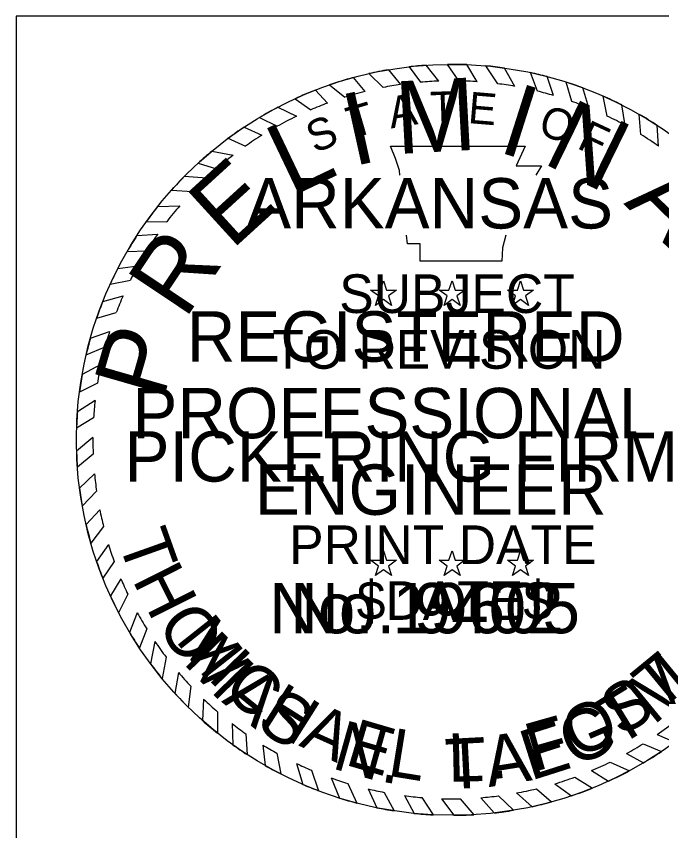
# Model space of a CAD drawing. Extents: x -0.3 to 2.65, y 0 to 1.9.
# Drawn here: x 1.2521 to 1.3416, y 0.0906 to 0.2035 of the extents above; entities that cross this region are included whole.
import ezdxf

# ---------------------------------------------------------------- set-up
doc = ezdxf.new("R2010")
doc.units = 0
for name, color, linetype in [('Level 50', 7, 'Continuous'), ('Level 51', 7, 'Continuous'), ('Level 53', 7, 'Continuous'), ('Level 55', 7, 'Continuous'), ('Level 56', 7, 'Continuous')]:
    doc.layers.add(name, color=color, linetype=linetype)

msp = doc.modelspace()

# ---------------------------------------------------------------- linework, layer by layer
at = {"layer": 'Level 50'}
msp.add_circle((1.3125000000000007, 0.14479166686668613), 0.05208333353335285, dxfattribs=at)
at = {"layer": 'Level 51'}
for p, q in [((1.3106664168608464, 0.194555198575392), (1.3089229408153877, 0.19675201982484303)), ((1.3134475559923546, 0.19457995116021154), (1.311890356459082, 0.1968714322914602)), ((1.3160059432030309, 0.19446539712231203), (1.314563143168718, 0.19683412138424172)), ((1.3188309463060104, 0.194184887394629), (1.3171991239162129, 0.19666258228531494)), ((1.3009818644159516, 0.19558542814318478), (1.302970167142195, 0.1936685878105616)), ((1.3036774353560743, 0.19612232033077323), (1.3053475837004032, 0.19407263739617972)), ((1.3065572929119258, 0.19653485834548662), (1.3081281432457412, 0.19439668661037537)), ((1.3212101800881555, 0.19382128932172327), (1.3197727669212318, 0.19636472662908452)), ((1.3243517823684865, 0.19315804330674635), (1.3233797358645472, 0.19572598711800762)), ((1.298814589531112, 0.19504485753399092), (1.3004232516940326, 0.19310236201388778)), ((1.3265952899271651, 0.1925524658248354), (1.3257055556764, 0.19517308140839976)), ((1.3291194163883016, 0.19173382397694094), (1.328330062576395, 0.19441104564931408)), ((1.2935701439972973, 0.19331314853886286), (1.2952165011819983, 0.19149339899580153)), ((1.2955130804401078, 0.19402700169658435), (1.297640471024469, 0.19232024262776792)), ((1.331456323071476, 0.19083978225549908), (1.3306495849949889, 0.19361037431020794)), ((1.2907339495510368, 0.19210881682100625), (1.2929100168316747, 0.1905737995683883)), ((1.3340336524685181, 0.1896923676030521), (1.3334594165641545, 0.19247160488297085)), ((1.2883261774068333, 0.19092516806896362), (1.2909151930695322, 0.18966779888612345)), ((1.3365237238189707, 0.18841083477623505), (1.3360376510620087, 0.19125296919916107)), ((1.3386891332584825, 0.18714612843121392), (1.3384674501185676, 0.18993992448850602)), ((1.2858233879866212, 0.18952456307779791), (1.288237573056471, 0.18827851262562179)), ((1.2836624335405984, 0.1881629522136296), (1.286130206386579, 0.18703388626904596)), ((1.3411167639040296, 0.18554521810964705), (1.3409425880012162, 0.18842299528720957)), ((1.281313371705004, 0.18667315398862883), (1.2838591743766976, 0.185528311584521)), ((1.3039685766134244, 0.18552625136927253), (1.3226514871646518, 0.18552625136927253)), ((1.3046465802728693, 0.18380893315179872), (1.3039685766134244, 0.18552625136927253)), ((1.3226514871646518, 0.18552625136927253), (1.3213951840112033, 0.18277854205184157)), ((1.2792080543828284, 0.18484563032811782), (1.2821648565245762, 0.18428280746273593)), ((1.277287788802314, 0.18316840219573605), (1.2798508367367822, 0.18239224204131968)), ((1.305227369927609, 0.18214612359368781), (1.3046465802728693, 0.18380893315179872)), ((1.3052674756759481, 0.18150686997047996), (1.305227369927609, 0.18214612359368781)), ((1.3213951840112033, 0.18277854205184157), (1.3249286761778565, 0.18277854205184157)), ((1.3249286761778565, 0.18277854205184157), (1.3241190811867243, 0.18150686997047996)), ((1.2754139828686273, 0.18136079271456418), (1.2784538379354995, 0.1811321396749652)), ((1.2736106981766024, 0.17943695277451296), (1.2765244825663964, 0.17922324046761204)), ((1.27167949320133, 0.17713915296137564), (1.274746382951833, 0.17726373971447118)), ((1.270125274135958, 0.17507460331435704), (1.2729470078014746, 0.17504611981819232)), ((1.2688156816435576, 0.17315280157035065), (1.2716986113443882, 0.17334018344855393)), ((1.3063358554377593, 0.17195943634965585), (1.3061890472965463, 0.1731743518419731)), ((1.3199533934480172, 0.1731743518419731), (1.3195182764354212, 0.17144424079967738)), ((1.308091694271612, 0.17195943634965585), (1.3063358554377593, 0.17195943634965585)), ((1.308091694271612, 0.16955519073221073), (1.308091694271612, 0.17195943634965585)), ((1.2674404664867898, 0.17091277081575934), (1.270172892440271, 0.1710249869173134)), ((1.3195182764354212, 0.17144424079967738), (1.3194308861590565, 0.16955519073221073)), ((1.3194308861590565, 0.16955519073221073), (1.308091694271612, 0.16955519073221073)), ((1.2661496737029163, 0.16854710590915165), (1.2689330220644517, 0.16890990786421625)), ((1.2650990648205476, 0.16637464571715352), (1.2679063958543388, 0.16695428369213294)), ((1.3025906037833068, 0.16554957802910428), (1.3030139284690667, 0.16685243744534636)), ((1.3030139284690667, 0.16685243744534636), (1.3034372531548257, 0.16554957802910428)), ((1.3120766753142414, 0.16554957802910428), (1.3125000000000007, 0.16685243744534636)), ((1.3125000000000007, 0.16685243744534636), (1.3129233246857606, 0.16554957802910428)), ((1.3215627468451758, 0.16554957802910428), (1.3219860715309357, 0.16685243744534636)), ((1.3219860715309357, 0.16685243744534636), (1.3224093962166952, 0.16554957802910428)), ((1.3023289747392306, 0.16474436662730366), (1.3012206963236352, 0.16554957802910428)), ((1.3012206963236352, 0.16554957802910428), (1.3025906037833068, 0.16554957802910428)), ((1.3034372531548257, 0.16554957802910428), (1.3048071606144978, 0.16554957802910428)), ((1.3048071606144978, 0.16554957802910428), (1.303698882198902, 0.16474436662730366)), ((1.3118150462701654, 0.16474436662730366), (1.3107067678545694, 0.16554957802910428)), ((1.3107067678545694, 0.16554957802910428), (1.3120766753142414, 0.16554957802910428)), ((1.3129233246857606, 0.16554957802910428), (1.3142932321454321, 0.16554957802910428)), ((1.3142932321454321, 0.16554957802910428), (1.3131849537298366, 0.16474436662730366)), ((1.3213011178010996, 0.16474436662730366), (1.3201928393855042, 0.16554957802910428)), ((1.3201928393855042, 0.16554957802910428), (1.3215627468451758, 0.16554957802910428)), ((1.3224093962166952, 0.16554957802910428), (1.3237793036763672, 0.16554957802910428)), ((1.3237793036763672, 0.16554957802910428), (1.3226710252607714, 0.16474436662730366)), ((1.2640715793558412, 0.16395834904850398), (1.2668884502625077, 0.1647756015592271)), ((1.3019056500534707, 0.1634415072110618), (1.3023289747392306, 0.16474436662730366)), ((1.3030139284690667, 0.16424671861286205), (1.3019056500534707, 0.1634415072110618)), ((1.3041222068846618, 0.1634415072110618), (1.3030139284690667, 0.16424671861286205)), ((1.303698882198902, 0.16474436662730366), (1.3041222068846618, 0.1634415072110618)), ((1.3113917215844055, 0.1634415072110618), (1.3118150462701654, 0.16474436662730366)), ((1.3125000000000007, 0.16424671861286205), (1.3113917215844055, 0.1634415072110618)), ((1.3136082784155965, 0.1634415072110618), (1.3125000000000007, 0.16424671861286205)), ((1.3131849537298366, 0.16474436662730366), (1.3136082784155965, 0.1634415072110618)), ((1.32087779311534, 0.1634415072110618), (1.3213011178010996, 0.16474436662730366)), ((1.3219860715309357, 0.16424671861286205), (1.32087779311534, 0.1634415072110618)), ((1.323094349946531, 0.1634415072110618), (1.3219860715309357, 0.16424671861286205)), ((1.3226710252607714, 0.16474436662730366), (1.323094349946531, 0.1634415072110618)), ((1.263233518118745, 0.1616880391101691), (1.2659383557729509, 0.1624490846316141)), ((1.262358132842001, 0.15887949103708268), (1.26502498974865, 0.15982145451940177)), ((1.2617733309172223, 0.156601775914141), (1.264399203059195, 0.1576790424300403)), ((1.2638081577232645, 0.15522601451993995), (1.2612078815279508, 0.15383557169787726)), ((1.263328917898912, 0.15266413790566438), (1.2608402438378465, 0.15142063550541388)), ((1.2630005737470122, 0.15023022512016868), (1.2605604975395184, 0.14865970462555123)), ((1.2627970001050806, 0.14785482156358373), (1.2604421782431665, 0.14642164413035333)), ((1.2627036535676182, 0.14509988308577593), (1.2604402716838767, 0.14322376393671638)), ((1.262741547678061, 0.14282506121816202), (1.2605540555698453, 0.14101112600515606)), ((1.262928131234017, 0.14005870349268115), (1.260852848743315, 0.13806519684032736)), ((1.2632160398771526, 0.13765987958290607), (1.2612386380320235, 0.1355750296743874)), ((1.2636557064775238, 0.13509599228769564), (1.261759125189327, 0.13304274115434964)), ((1.2641789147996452, 0.13275655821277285), (1.2624336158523, 0.13043789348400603)), ((1.2648703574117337, 0.13025934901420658), (1.2632237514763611, 0.12792379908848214)), ((1.3025906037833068, 0.12807935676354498), (1.3030139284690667, 0.12938221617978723)), ((1.3030139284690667, 0.12938221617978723), (1.3034372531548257, 0.12807935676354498)), ((1.3120766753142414, 0.12807935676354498), (1.3125000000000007, 0.12938221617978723)), ((1.3125000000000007, 0.12938221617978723), (1.3129233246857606, 0.12807935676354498)), ((1.3215627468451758, 0.12807935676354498), (1.3219860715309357, 0.12938221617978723)), ((1.3219860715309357, 0.12938221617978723), (1.3224093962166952, 0.12807935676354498)), ((1.2656570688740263, 0.12789459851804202), (1.264083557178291, 0.12559474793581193)), ((1.3023289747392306, 0.12727414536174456), (1.3012206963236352, 0.12807935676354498)), ((1.3012206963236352, 0.12807935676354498), (1.3025906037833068, 0.12807935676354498)), ((1.3034372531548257, 0.12807935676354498), (1.3048071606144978, 0.12807935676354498)), ((1.3048071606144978, 0.12807935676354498), (1.303698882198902, 0.12727414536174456)), ((1.3118150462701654, 0.12727414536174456), (1.3107067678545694, 0.12807935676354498)), ((1.3107067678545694, 0.12807935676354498), (1.3120766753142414, 0.12807935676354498)), ((1.3129233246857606, 0.12807935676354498), (1.3142932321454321, 0.12807935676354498)), ((1.3142932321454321, 0.12807935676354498), (1.3131849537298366, 0.12727414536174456)), ((1.3213011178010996, 0.12727414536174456), (1.3201928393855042, 0.12807935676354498)), ((1.3201928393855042, 0.12807935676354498), (1.3215627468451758, 0.12807935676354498)), ((1.3224093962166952, 0.12807935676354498), (1.3237793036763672, 0.12807935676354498)), ((1.3237793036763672, 0.12807935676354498), (1.3226710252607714, 0.12727414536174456)), ((1.3019056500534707, 0.12597128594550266), (1.3023289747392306, 0.12727414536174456)), ((1.3030139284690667, 0.12677649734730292), (1.3019056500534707, 0.12597128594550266)), ((1.3041222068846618, 0.12597128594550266), (1.3030139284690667, 0.12677649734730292)), ((1.303698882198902, 0.12727414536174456), (1.3041222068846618, 0.12597128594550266)), ((1.3113917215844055, 0.12597128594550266), (1.3118150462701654, 0.12727414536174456)), ((1.3125000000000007, 0.12677649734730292), (1.3113917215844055, 0.12597128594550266)), ((1.3136082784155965, 0.12597128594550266), (1.3125000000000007, 0.12677649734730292)), ((1.3131849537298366, 0.12727414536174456), (1.3136082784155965, 0.12597128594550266)), ((1.32087779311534, 0.12597128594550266), (1.3213011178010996, 0.12727414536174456)), ((1.3219860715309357, 0.12677649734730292), (1.32087779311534, 0.12597128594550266)), ((1.323094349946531, 0.12597128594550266), (1.3219860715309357, 0.12677649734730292)), ((1.3226710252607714, 0.12727414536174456), (1.323094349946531, 0.12597128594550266)), ((1.2665856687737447, 0.125513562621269), (1.2651242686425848, 0.12315342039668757)), ((1.267545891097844, 0.12336973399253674), (1.266273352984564, 0.12079644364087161)), ((1.268857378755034, 0.12081057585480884), (1.2677921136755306, 0.11807316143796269)), ((1.270174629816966, 0.11855554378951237), (1.2691474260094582, 0.11592597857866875)), ((1.2713056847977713, 0.11681311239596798), (1.2706928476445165, 0.113729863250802)), ((1.2728742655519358, 0.11463255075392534), (1.2723060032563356, 0.11166892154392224)), ((1.274572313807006, 0.11252307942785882), (1.274087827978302, 0.10961811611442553)), ((1.276262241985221, 0.11063619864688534), (1.2759166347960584, 0.10771969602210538)), ((1.278064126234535, 0.10882026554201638), (1.2778977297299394, 0.10586408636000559)), ((1.2799881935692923, 0.10707226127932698), (1.2799693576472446, 0.10411697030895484)), ((1.2819988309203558, 0.10542861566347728), (1.2821035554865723, 0.10249828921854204)), ((1.2838901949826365, 0.10403323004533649), (1.2840915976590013, 0.10113807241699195)), ((1.3409364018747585, 0.10391206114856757), (1.3433867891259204, 0.10285504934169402)), ((1.2862754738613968, 0.10245911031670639), (1.2866141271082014, 0.09959658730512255)), ((1.3390154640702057, 0.10264073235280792), (1.3415267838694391, 0.10154678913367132)), ((1.288232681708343, 0.10130755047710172), (1.2887423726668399, 0.09844246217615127)), ((1.3367005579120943, 0.10127036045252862), (1.3390290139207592, 0.09997107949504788)), ((1.2909209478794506, 0.09991276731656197), (1.2917951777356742, 0.09700062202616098)), ((1.3344222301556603, 0.10007939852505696), (1.3371253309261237, 0.09889758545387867)), ((1.2930015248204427, 0.09897048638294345), (1.293967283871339, 0.0961171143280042)), ((1.3318569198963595, 0.09891050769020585), (1.3342210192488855, 0.09745382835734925)), ((1.2957537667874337, 0.09789460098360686), (1.2969220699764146, 0.0950925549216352)), ((1.329513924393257, 0.09799105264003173), (1.3319882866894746, 0.09649176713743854)), ((1.2980417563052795, 0.09713948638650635), (1.2993055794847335, 0.09440733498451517)), ((1.3008793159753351, 0.09636924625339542), (1.3020657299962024, 0.09376422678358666)), ((1.3241937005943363, 0.09638682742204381), (1.3263049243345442, 0.09457117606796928)), ((1.3267617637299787, 0.09708031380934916), (1.3290873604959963, 0.09542028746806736)), ((1.3030999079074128, 0.09588962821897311), (1.3044779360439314, 0.09332983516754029)), ((1.305895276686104, 0.09543430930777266), (1.3072346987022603, 0.09297516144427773)), ((1.308334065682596, 0.09516892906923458), (1.309865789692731, 0.0927749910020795)), ((1.311041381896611, 0.09501573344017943), (1.3127316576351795, 0.09270884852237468)), ((1.3136097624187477, 0.09500673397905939), (1.3155308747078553, 0.09279659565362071)), ((1.316507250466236, 0.09515586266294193), (1.3183272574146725, 0.0930353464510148)), ((1.3189555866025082, 0.09541458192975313), (1.321038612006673, 0.09341301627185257)), ((1.3214431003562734, 0.09580399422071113), (1.3236130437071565, 0.09390774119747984))]:
    msp.add_line(p, q, dxfattribs=at)
for radius, start, end in [(0.05208333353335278, 93.93814766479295, 96.55171575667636), (0.05208333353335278, 87.72978562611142, 90.67067134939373), (0.05208333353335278, 81.97315125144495, 84.82355346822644), (0.05208333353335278, 99.75254266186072, 102.77648138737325), (0.05208333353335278, 75.31251453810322, 77.94263429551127), (0.05208333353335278, 105.2338868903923, 109.03519250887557), (0.04979730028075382, 92.11016115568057, 95.0366553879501), (0.04979730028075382, 85.96279180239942, 88.90969519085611), (0.05208333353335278, 69.60611387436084, 72.30576523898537), (0.05208333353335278, 111.31242303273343, 114.70259160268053), (0.04979730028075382, 98.25798851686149, 101.03289140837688), (0.04979730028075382, 79.92642235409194, 82.69597271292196), (0.04979730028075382, 104.03521042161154, 107.3615463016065), (0.04979730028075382, 73.55748025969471, 76.23144174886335), (0.05208333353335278, 63.13287778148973, 66.27039835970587), (0.05208333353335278, 117.65440981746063, 120.8098782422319), (0.04979730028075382, 110.30863674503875, 113.1658795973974), (0.04979730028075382, 67.62482877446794, 70.50398398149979), (0.05208333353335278, 56.90029228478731, 60.09422987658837), (0.04979730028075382, 115.68691928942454, 119.15826889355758), (0.04979730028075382, 61.155754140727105, 64.37837449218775), (0.05208333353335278, 123.61993215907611, 126.59062794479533), (0.04979730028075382, 121.97455773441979, 125.1100085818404), (0.04979730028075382, 54.923827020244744, 58.27015777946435), (0.05208333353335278, 129.73259019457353, 132.53764328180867), (0.04979730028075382, 127.5296898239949, 130.96828939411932), (0.05208333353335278, 135.40207922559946, 138.30313604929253), (0.04979730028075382, 133.13305755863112, 136.25622701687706), (0.05208333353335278, 141.60555977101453, 144.4486483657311), (0.04979730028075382, 139.30101253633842, 142.58728849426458), (0.05208333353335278, 147.00719016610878, 149.8990425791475), (0.04979730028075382, 145.0197202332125, 148.2103639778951), (0.05208333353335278, 152.8639823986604, 155.51889127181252), (0.04979730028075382, 151.03152721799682, 153.57304034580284), (0.05208333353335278, 158.40765685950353, 161.07014519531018), (0.04979730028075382, 156.3401777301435, 159.23193612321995), (0.04979730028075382, 162.43309106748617, 165.00132712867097), (0.05208333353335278, 164.306798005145, 166.89395340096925), (0.04979730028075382, 167.9048137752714, 170.90393120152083), (0.05208333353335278, 170.00030285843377, 172.68777762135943), (0.04979730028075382, 173.72999663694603, 176.47336897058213), (0.05208333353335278, 175.7409317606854, 178.20660347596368), (0.04979730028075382, 179.64537030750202, 182.26332578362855), (0.05208333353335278, 181.72507764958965, 184.1625542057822), (0.04979730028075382, 185.45388553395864, 188.23400522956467), (0.05208333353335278, 187.4203742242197, 190.19270523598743), (0.04979730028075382, 191.22736344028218, 193.98583171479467), (0.05208333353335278, 193.03694969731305, 195.99732329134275), (0.04979730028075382, 196.96751323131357, 199.83526481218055), (0.05208333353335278, 198.89670805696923, 201.62812073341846), (0.04979730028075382, 202.77613115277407, 205.4791499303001), (0.05208333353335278, 204.54793110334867, 207.4328212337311), (0.04979730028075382, 208.78826076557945, 211.79343039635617), (0.05208333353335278, 210.86355209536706, 213.65709060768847), (0.04979730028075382, 214.1837527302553, 217.27473515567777), (0.05208333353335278, 216.6115448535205, 219.49097786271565), (0.04979730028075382, 220.3908842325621, 223.30563758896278), (0.05208333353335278, 222.47995056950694, 225.38007606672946), (0.04979730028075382, 226.24937804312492, 229.24068458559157), (0.05208333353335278, 228.36647999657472, 231.34802159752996), (0.04979730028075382, 232.22904076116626, 234.9336099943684), (0.04979730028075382, 304.8229923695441, 308.51427595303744), (0.05208333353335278, 234.2950242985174, 236.94517274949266), (0.04979730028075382, 238.22226702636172, 240.83528634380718), (0.04979730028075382, 299.0767860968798, 302.17235325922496), (0.05208333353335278, 300.6210136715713, 303.87026284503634), (0.05208333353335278, 240.19770246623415, 242.8612773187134), (0.04979730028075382, 244.32042796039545, 246.94859267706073), (0.04979730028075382, 292.87451949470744, 296.11851166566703), (0.05208333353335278, 294.64807577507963, 298.2166176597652), (0.04979730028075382, 250.34912199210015, 253.1215727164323), (0.04979730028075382, 286.6423316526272, 289.9782614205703), (0.05208333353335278, 246.5759811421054, 249.15579179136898), (0.04979730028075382, 256.50504644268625, 259.1191575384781), (0.04979730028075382, 280.345883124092, 283.58136600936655), (0.05208333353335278, 288.5708646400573, 291.9733383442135), (0.05208333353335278, 252.59666978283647, 255.3251775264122), (0.04979730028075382, 262.37827883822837, 265.2011504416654), (0.04979730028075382, 268.32150305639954, 271.2769761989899), (0.04979730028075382, 274.6156530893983, 277.44863267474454), (0.05208333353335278, 258.4432759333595, 261.13982575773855), (0.05208333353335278, 282.3199420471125, 285.3701939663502), (0.05208333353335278, 264.1978410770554, 267.1009237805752), (0.05208333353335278, 270.25484253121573, 273.33608620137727), (0.05208333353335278, 276.4238933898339, 279.4357408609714)]:
    msp.add_arc((1.3125000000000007, 0.14479166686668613), radius, start, end, dxfattribs=at)
at = {"layer": 'Level 56'}
msp.add_lwpolyline([(1.3712499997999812, 0.2035416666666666), (1.2520833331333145, 0.2035416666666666), (1.2520833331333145, 0.08437499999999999), (1.3712499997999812, 0.08437499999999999)], close=True, dxfattribs=at)

# ---------------------------------------------------------------- texts
at = {"layer": 'Level 50'}
for s, rotation, p in [('M', 3.107384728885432, (1.3048781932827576, 0.18443386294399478)), ('I', 342.3163708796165, (1.3186635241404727, 0.18481031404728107)), ('I', 12.524847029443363, (1.2987433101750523, 0.18270651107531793)), ('N', 333.93819993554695, (1.3248520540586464, 0.18327946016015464)), ('L', 25.513048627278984, (1.2902020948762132, 0.17846557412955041)), ('E', 42.3578427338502, (1.2819189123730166, 0.17102941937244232)), ('A', 315.65789090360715, (1.3362148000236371, 0.17755060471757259)), ('R', 56.22922398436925, (1.2754632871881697, 0.16134985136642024)), ('P', 73.91301312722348, (1.2723945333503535, 0.15004546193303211))]:
    msp.add_text(s, height=0.010056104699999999, rotation=rotation, dxfattribs=at).set_placement(p)
for s, height, p in [('SUBJECT', 0.005363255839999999, (1.296857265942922, 0.16238601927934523)), ('TO REVISION', 0.005363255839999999, (1.2875569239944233, 0.15465015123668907)), ('PICKERING FIRM', 0.006983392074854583, (1.2670979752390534, 0.13899943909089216)), ('PRINT DATE', 0.005363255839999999, (1.2899156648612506, 0.1275588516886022)), ('$DATE$', 0.005363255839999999, (1.299282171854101, 0.11982298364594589))]:
    msp.add_text(s, height=height, dxfattribs=at).set_placement(p)
at = {"layer": 'Level 51'}
for s, height, rotation, p in [('A', 0.004364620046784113, 9.067898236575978, (1.3040301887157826, 0.18797032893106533)), ('T', 0.0043646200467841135, 1.824794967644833, (1.3095417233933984, 0.18869363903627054)), ('E', 0.004364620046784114, 355.2001929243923, (1.3146261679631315, 0.18874179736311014)), ('T', 0.004364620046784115, 16.311001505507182, (1.298653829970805, 0.18655789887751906)), ('O', 0.004364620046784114, 342.25064860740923, (1.324272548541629, 0.1871951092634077)), ('S', 0.004364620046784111, 23.55410477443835, (1.2934984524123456, 0.18447889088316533)), ('F', 0.0043646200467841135, 335.00754533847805, (1.329666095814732, 0.18530659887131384))]:
    msp.add_text(s, height=height, rotation=rotation, dxfattribs=at).set_placement(p)
for s, p in [('ARKANSAS', (1.2839647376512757, 0.17410696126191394)), ('REGISTERED', (1.2757208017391, 0.1556353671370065)), ('PROFESSIONAL', (1.2681887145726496, 0.14501247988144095)), ('ENGINEER', (1.2851749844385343, 0.13438959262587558))]:
    msp.add_text(s, height=0.006983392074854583, dxfattribs=at).set_placement(p)
at = {"layer": 'Level 53'}
msp.add_text('No. 9402', height=0.006983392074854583, dxfattribs=at).set_placement((1.290073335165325, 0.11795939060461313))
for s, height, rotation, p in [('M', 0.006704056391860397, 308.3390181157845, (1.2740407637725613, 0.11698071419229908)), ('I', 0.006704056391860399, 314.1842317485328, (1.278497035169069, 0.11174343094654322)), ('T', 0.006704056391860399, 39.41937898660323, (1.3412284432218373, 0.10702580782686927)), ('C', 0.006704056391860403, 319.87326798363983, (1.2804759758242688, 0.10976998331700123)), ('H', 0.006704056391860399, 327.7234907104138, (1.2856674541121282, 0.1056560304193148)), ('S', 0.0067040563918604, 31.72335532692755, (1.335912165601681, 0.10351874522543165)), ('O', 0.006704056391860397, 23.718966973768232, (1.3297030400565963, 0.10055799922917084)), ('A', 0.006704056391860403, 335.72761050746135, (1.2911454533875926, 0.10240599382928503)), ('F', 0.0067040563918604, 15.869077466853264, (1.323868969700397, 0.09872769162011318)), ('E', 0.006704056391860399, 343.5779028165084, (1.2975022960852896, 0.09977820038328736)), ('L', 0.006704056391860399, 350.81147507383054, (1.3034155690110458, 0.09822763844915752)), ('L', 0.006704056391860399, 1.2665847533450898, (1.312016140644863, 0.09735221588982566)), ('.', 0.006704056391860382, 6.803540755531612, (1.3178636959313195, 0.09767814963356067))]:
    msp.add_text(s, height=height, rotation=rotation, dxfattribs=at).set_placement(p)
at = {"layer": 'Level 55'}
for s, height, rotation, p in [('T', 0.006983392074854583, 289.64596820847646, (1.2660987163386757, 0.13088211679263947)), ('H', 0.0069833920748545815, 296.73386139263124, (1.268109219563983, 0.12538216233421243)), ('O', 0.006983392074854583, 303.7707760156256, (1.2714213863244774, 0.11919222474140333)), ('M', 0.006983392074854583, 314.203293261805, (1.2750806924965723, 0.1138779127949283)), ('M', 0.00698339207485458, 39.30004668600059, (1.3404223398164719, 0.10511583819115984)), ('A', 0.006983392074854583, 321.05939598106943, (1.2804521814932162, 0.10848903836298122)), ('T', 0.00698339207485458, 31.466005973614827, (1.3354052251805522, 0.10208014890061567)), ('S', 0.006983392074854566, 327.82385093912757, (1.2850689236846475, 0.10489215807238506)), ('G', 0.00698339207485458, 23.30524175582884, (1.3292590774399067, 0.09932653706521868)), ('N', 0.006983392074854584, 344.27272867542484, (1.2956650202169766, 0.09926973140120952)), ('E', 0.006983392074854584, 17.683629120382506, (1.3233935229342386, 0.09747987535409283)), ('A', 0.0069833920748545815, 8.9826070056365, (1.3175889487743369, 0.0966112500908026)), ('T', 0.006983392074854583, 3.006085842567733, (1.3117410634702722, 0.09630184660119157)), ('.', 0.0069833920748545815, 350.64642779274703, (1.3024405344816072, 0.0974149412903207))]:
    msp.add_text(s, height=height, rotation=rotation, dxfattribs=at).set_placement(p)
msp.add_text('No. 19605', height=0.006983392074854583, dxfattribs=at).set_placement((1.2871469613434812, 0.11795939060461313))

doc.saveas('drawing.dxf')
